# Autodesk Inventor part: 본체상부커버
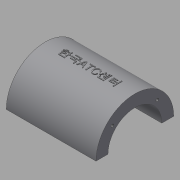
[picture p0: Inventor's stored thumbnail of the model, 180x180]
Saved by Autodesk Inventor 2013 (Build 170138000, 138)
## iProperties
Created: 2015-12
Part Number: 본체상부커버
Material: 일반
Document SubType Name: Modeling
Designer: mduedu
Density: 2.71 g/cm^3
Author: mduedu
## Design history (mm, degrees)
sketch "스케치1"
  geometry: L1 (45, 40)-(-45, 40); L2 (-45, 40)-(-45, -40); L3 (-45, -40)-(45, -40); L4 (45, -40)-(45, 40); L5 (45, 40)-(-45, -40); L6 (-45, 40)-(45, -40); 2 further points
  constraints: 12 end point, 2 midpoint, 2 parallel, 1 coincident, 1 horizontal, 1 perpendicular, 3 other
  dimensions: "d0" = 90 distance of L2.end L3.end; "d2" = 80 distance of L1.end L2.end
extrude "돌출1" new body sketch "스케치1" distance "d3" = 10; taper "d4" = 0 deg
sketch "스케치2"
  geometry: C1 r 32.5 at (80, 0); 1 further point
  constraints: 1 centre point
  dimensions: "d5" = 65 diameter of C1; "d116" = 80 distance of point (0, 0) C1.centre
extrude "돌출2" join sketch "스케치2" stored distance "d7" = 75; taper "d8" = 0 deg
sketch "스케치3"
  geometry: L1 (-27.5, -20)-(27.5, -20); L2 (27.5, -20)-(27.5, 20); L3 (27.5, 20)-(-27.5, 20); L4 (-27.5, 20)-(-27.5, -20); L5 (-27.5, -20)-(27.5, 20); L6 (27.5, -20)-(-27.5, 20); 1 further point
  constraints: 12 end point, 2 midpoint, 2 parallel, 1 horizontal, 1 perpendicular
  dimensions: "d9" = 55 distance of L2.end L3.end; "d11" = 40 distance of L1.end L2.end
extrude "돌출3" new body sketch "스케치3" stored distance "d12" = 75; taper "d13" = 0 deg
fillet "모깎기1"
fillet "모깎기2"
feature "결합1"
  node "솔리드2"
sketch "스케치4"
  geometry: L1 (-37.5, 47.5)-(37.5, 47.5) reference; L2 (32.5, 47.5)-(40.208, 10); L3 (37.5, 47.5)-(37.5, 112.5) reference; L4 (60.208, 0)-(60.208, 10) reference; L5 (60.208, 10)-(-60.208, 10) reference; 1 further point
  constraints: 2 end point, 2 point on line
  dimensions: "d15" = 5 distance from line of L2.start L3; "d117" = 20 distance from line of L2.end L4
sketch "스케치5"
  geometry: L1 (10, 35.208)-(56.729, 22.687); L2 (0, 60.208)-(10, 60.208) reference; L3 (10, -60.208)-(10, 60.208) reference; 2 further points
  constraints: 2 end point, 1 point on line, 2 other
  dimensions: "d118" = 25 distance from line of L1.start L2; "d119" = 75 deg angle of L1 L3
feature "리브1" dims "d19" = 1, "d20" = 6, "d21" = 0, "d22" = 0, "d23" = 1, "d24" = 1
feature "리브2" dims "d25" = 1, "d26" = 6, "d27" = 0, "d28" = 0, "d29" = 1, "d30" = 1
fillet "모깎기4" dims "d31" = 2
fillet "모깎기5" dims "d32" = 2
fillet "모깎기6" dims "d33" = 2
sketch "스케치6"
  geometry: L1 (0, 0)-(-32.88, 32.88); L2 (0, 0)-(-46.5, 0); A1 r 46.5 centre (0, 0) between (-32.88, 32.88) and (-46.5, 0); 5 further points
  constraints: 4 end point, 2 coincident, 2 point on circle, 1 centre point, 1 horizontal, 5 other
  dimensions: "d120" = 93 diameter of A1; "d122" = 45 deg angle of L1 L2; "d126" = 360 deg dimension on point (0, 0) point (-32.88, 32.88) (derived)
hole "구멍1" sketch "스케치6" at (-32.88, 32.88), (-32.88, -32.88), (32.88, -32.88), (32.88, 32.88) diameter "d34" = 7; stored, may be unused: countersink angle "d38" = 90 deg, drill point angle "d40" = 118 deg; dims "d35" = 6, "d36" = 12, "d37" = 3, "d39" = 8
fillet "모깎기13" dims "d131" = 3
hole "구멍2" diameter "d44" = 45; stored, may be unused: countersink angle "d48" = 90 deg, drill point angle "d50" = 118 deg; dims "d42" = 10, "d43" = 10, "d45" = 6, "d46" = 4, "d47" = 2, "d49" = 8
sketch "스케치7" dims "d52" = 26.5
  geometry: L1 (0, 0)-(32.5, 0); L2 (0, 0)-(22.981, 22.981); A1 r 32.5 centre (0, 0) between (32.5, 0) and (22.981, 22.981) reference; 3 further points
  constraints: 4 end point, 2 point on circle, 1 coincident, 1 horizontal, 1 point on line, 3 other
  dimensions: "d51" = 45 deg angle of L2 L1
hole "구멍3" sketch "스케치7" at (18.738, 18.738) diameter "d54" = 2.459; stored, may be unused: countersink angle "d58" = 90 deg, drill point angle "d60" = 118 deg; dims "d55" = 8, "d56" = 4, "d57" = 2, "d59" = 10
sketch "스케치9"
  geometry: L1 (-75, -110)-(75, -110); L2 (75, -110)-(75, 0); L3 (75, 0)-(-75, 0); L4 (-75, 0)-(-75, -110); L5 (-60.208, -80)-(60.208, -80) reference; C1 r 32.5 at (0, 0) reference; 2 further points
  constraints: 8 end point, 2 parallel, 1 coincident, 1 horizontal, 1 midpoint, 1 perpendicular
  dimensions: "d148" = 30 distance between parallel lines of L5 L1; "d159" = 150 distance between parallel lines of L2 L4
extrude "돌출5" cut sketch "스케치9" stored distance "d73" = 0; taper "d74" = 0 deg
node "작업 평면3"
sketch "스케치17" dims "d2" = 80
  geometry: 2 further points
  constraints: 1 coincident, 1 other
feature "엠보싱1" sketch "스케치17" dims "d0" = 90, "d2" = 80, "d150" = 0.5, "d151" = 0
node "솔리드1"
mirror "대칭1"
mirror "대칭2"
pattern_circular "원형 패턴1" dims angle "d62" = 360 deg
mirror "대칭3"
